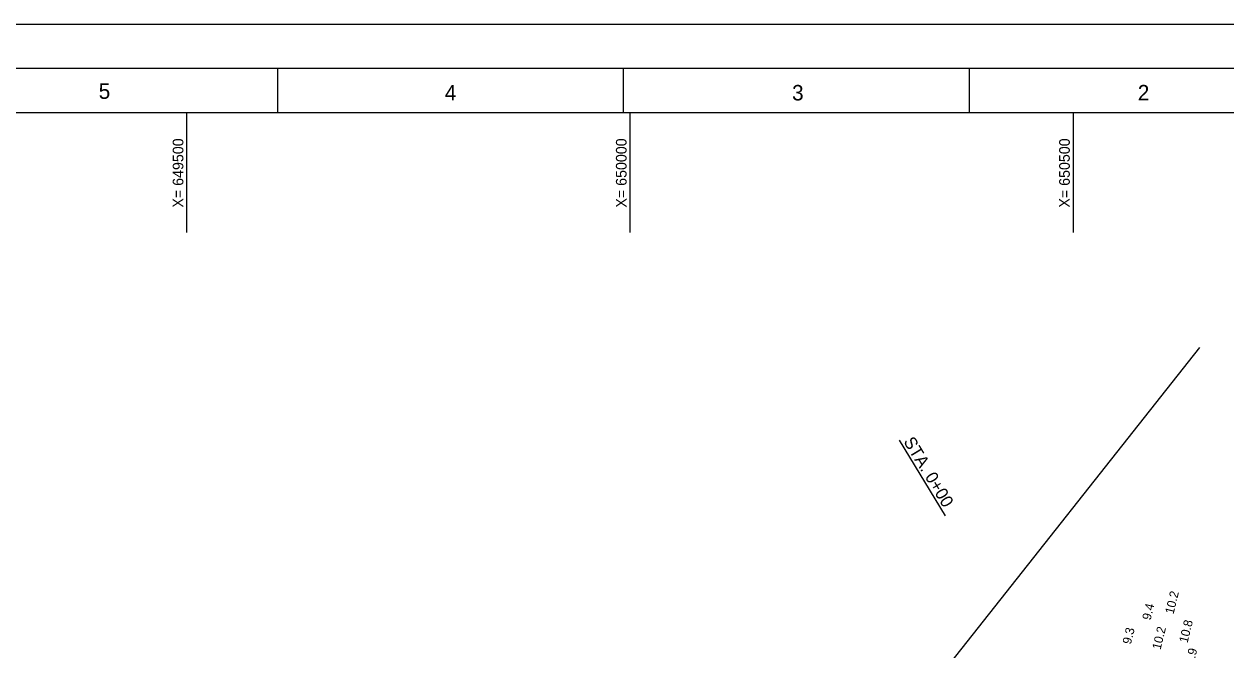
# Model space of a CAD drawing. Extents: x 647087 to 651487, y 788838 to 792238.
# Drawn here: x 649316 to 650672, y 791532 to 792238 of the extents above; entities that cross this region are included whole.
import ezdxf

# ---------------------------------------------------------------- set-up
doc = ezdxf.new("R2010")
doc.units = 0
for name, color, linetype in [('C-CHAN-WIDE', 7, 'Continuous'), ('G-ANNO-NPLT', 7, 'Continuous'), ('G-ANNO-TTLB', 7, 'Continuous'), ('V-ALGN-TEXT', 7, 'Continuous'), ('V-TOPO-COOR-STAT', 7, 'Continuous'), ('V-TOPO-SOUN', 7, 'Continuous')]:
    doc.layers.add(name, color=color, linetype=linetype)

msp = doc.modelspace()

# ---------------------------------------------------------------- linework, layer by layer
at = {"layer": 'C-CHAN-WIDE'}
msp.add_line((650083.9, 791167.5), (650642.6, 791873.1), dxfattribs=at)
at = {"layer": 'G-ANNO-NPLT'}
msp.add_lwpolyline([(647087.3, 792237.8), (651487.3, 792237.8), (651487.3, 788837.9), (647087.3, 788837.9)], close=True, dxfattribs=at)
at = {"layer": 'G-ANNO-TTLB'}
for p, q in [((649602.3, 792187.8), (649602.3, 792137.8)), ((649992.3, 792187.8), (649992.3, 792137.8)), ((650382.3, 792187.8), (650382.3, 792137.8))]:
    msp.add_line(p, q, dxfattribs=at)
for points in [[(647137.3, 788887.9), (651437.3, 788887.9), (651437.3, 792187.8), (647137.3, 792187.8)], [(651387.3, 792137.8), (647262.3, 792137.8), (647262.3, 788937.9), (651387.3, 788937.9)]]:
    msp.add_lwpolyline(points, close=True, dxfattribs=at)
at = {"layer": 'V-ALGN-TEXT'}
msp.add_line((650303.6, 791768.9), (650355.5, 791683.4), dxfattribs=at)
at = {"layer": 'V-TOPO-COOR-STAT'}
for p, q in [((649500, 792002.8), (649500, 792137.8)), ((650000, 792002.8), (650000, 792137.8)), ((650500, 792002.8), (650500, 792137.8))]:
    msp.add_line(p, q, dxfattribs=at)

# ---------------------------------------------------------------- texts
at = {"layer": 'G-ANNO-TTLB'}
for s, p in [('5', (649400.5, 792153.5)), ('3', (650182.7, 792151.7)), ('2', (650572.7, 792151.7)), ('4', (649790.9, 792151.7))]:
    msp.add_text(s, height=17.5, dxfattribs=at).set_placement(p)
at = {"layer": 'V-ALGN-TEXT'}
msp.add_text('STA. 0+00', height=13.92, rotation=301.2715, dxfattribs=at).set_placement((650307.9, 791767.2))
at = {"layer": 'V-TOPO-COOR-STAT'}
for s, p in [('X= 649500', (649496, 792030.9)), ('X= 650000', (649996, 792030.9)), ('X= 650500', (650496, 792030.9))]:
    msp.add_text(s, height=12, rotation=90, dxfattribs=at).set_placement(p)
at = {"layer": 'V-TOPO-SOUN'}
for s, p in [('10.2 ', (650613, 791572)), ('9.4', (650587.1, 791565.2)), ('10.8 ', (650628.8, 791539.5)), ('9.3', (650564.9, 791538)), ('10.2 ', (650598.4, 791531.9)), ('10.9 ', (650633.8, 791507.6))]:
    msp.add_text(s, height=10, rotation=76.16, dxfattribs=at).set_placement(p)

doc.saveas('drawing.dxf')
